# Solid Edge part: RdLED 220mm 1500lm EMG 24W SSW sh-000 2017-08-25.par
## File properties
Author: lukasz.lemanski
Template: iso metric part.par
Last saved by: lukasz.lemanski
Revision: 1
Application: Solid Edge
Username: lukasz.lemanski
Gęstość: 0,000 kg/m^3
Dokładność: 0,990
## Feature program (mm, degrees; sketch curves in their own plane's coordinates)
body "unnamed Body 1"
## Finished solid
Body 1: solid body, 2024 faces, 5204 edges, 3346 vertices, 3 separate solids.
  Faces by surface: plane 1501, cylinder 237, spline 160, cone 52, torus 22, sphere 20, swept 18, spun 14
  Edges by curve: line 4072, curve on surface 600, circle 312, ellipse 132, spline 76, intersection 12
Bounding box of the edges (mm; curved faces can reach further): 210.000 x 4.500 x 210.000, from (-105, -3.5, -105) to (105, 1, 105).
Cylindrical faces by radius (mm): R0.2 x78, R0.2002 x4, R0.2169 x6, R0.25 x24, R0.3 x4, R0.3373 x6, R0.4 x16, R0.4006 x4, R0.4008 x4, R0.525 x4, R0.6 x24, R0.75 x4, R1 x19, R1.0894 x4, R1.1 x28, R2.15 x4, R110 x4
Conical faces (half-angle, radius in mm at the cone's reference point): 0.5 deg R0.5056 x8, 0.5 deg R1.0082 x8, 1 deg R0.5511 x4, 10 deg R0.2132 x4, 10 deg R0.4132 x4, 18.4844 deg R1.0657 x8, 27.363 deg R0.6214 x4, 45 deg R0.575 x4, 45 deg R0.625 x8
Toroidal faces (ring radius, tube radius in mm): R0.1 r0.2 x2, R0.8 r0.2 x8, R0.8522 r0.3 x4, R0.9002 r0.2 x2, R0.9018 r0.2 x2, R1.3 r0.2 x4
Spherical faces by radius (mm): R0.2 x16, R0.6 x4
Planar faces by outward normal: +x 58, +y 23, +z 57, -x 58, -y 262, -z 77, oblique 966
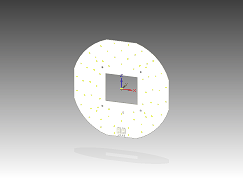
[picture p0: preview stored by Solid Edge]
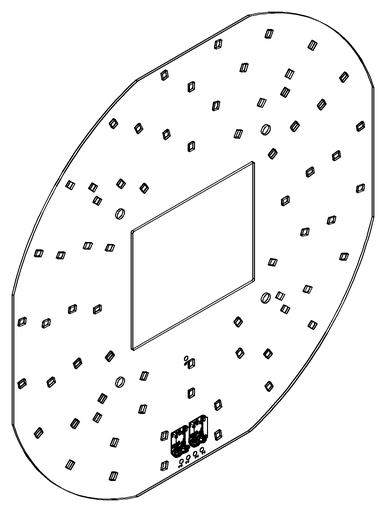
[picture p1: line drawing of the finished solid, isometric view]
